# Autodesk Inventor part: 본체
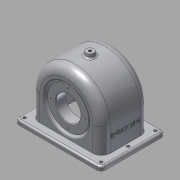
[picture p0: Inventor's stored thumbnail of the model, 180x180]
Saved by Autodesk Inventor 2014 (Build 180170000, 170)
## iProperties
Created: 2015-09
Part Number: 본체
Material: 알루미늄 6061
Document SubType Name: 판금
Designer: Owner
Density: 2.71 g/cm^3
Appearance: 알루미늄 - 평지
Sheet Metal Rule: 기본값
Author: Owner
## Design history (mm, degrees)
sketch "스케치1"
  geometry: L1 (-57, 38.5)-(57, 38.5); L2 (57, 38.5)-(57, -38.5); L3 (57, -38.5)-(-57, -38.5); L4 (-57, -38.5)-(-57, 38.5); 1 further point
  constraints: 8 end point, 2 parallel, 1 horizontal, 1 perpendicular
  dimensions: "d2" = 77 distance of L1.end L2.end; "d3" = 38.5 distance from line of L1 point (0, 0); "d4" = 114 distance of L2.end L3.end; "d8" = 57 distance from line of point (0, 0) L4
extrude "돌출1" new body sketch "스케치1" distance "d9" = 47; taper "d10" = 0 deg
sketch "스케치2"
  geometry: L1 (114, 0)-(114, 47) reference; L2 (0, 47)-(114, 47) reference; L3 (0, 47)-(114, 47); A1 r 57 centre (57, 47) between (114, 47) and (0, 47); 1 further point
  constraints: 3 point on circle, 2 end point, 2 point on line, 1 centre point, 1 midpoint, 1 perpendicular
  dimensions: "d11" = 114 diameter of A1 (derived)
extrude "돌출2" join sketch "스케치2" distance "d12" = 77; taper "d13" = 0 deg
feature "쉘1" dims "d14" = 5
fillet "모깎기1" dims "d15" = 9
sketch "스케치3"
  geometry: C1 r 31 at (57, 47); A1 r 57 centre (57, 47) between (114, 47) and (0, 47) reference; 1 further point
  constraints: 1 centre point, 1 coincident
  dimensions: "d16" = 62 diameter of C1
extrude "돌출3" join sketch "스케치3" distance "d17" = 10; taper "d18" = 0 deg
hole "구멍1" diameter "d21" = 40; stored, may be unused: countersink angle "d25" = 90 deg, drill point angle "d27" = 0 deg; dims "d19" = 10, "d20" = 10, "d22" = 6, "d23" = 4, "d24" = 2, "d26" = 8
chamfer "모따기1" distance "d28" = 1; stored, may be unused: second distance "d29" = 2, angle "d30" = 45 deg
sketch "스케치4"
  geometry: C1 r 31 at (0, 0) reference; 2 further points
  constraints: 1 vertical alignment
  dimensions: "d31" = 24 distance of C1.centre point (0, 24)
hole "구멍2" sketch "스케치4" at (0, 24) diameter "d32" = 2.459; stored, may be unused: countersink angle "d36" = 90 deg, drill point angle "d38" = 118 deg; dims "d33" = 6, "d34" = 4, "d35" = 2, "d37" = 8
sketch "스케치6"
  geometry: L1 (0, 47)-(25.941, 47); L2 (33.5, 47)-(33.5, 90) reference; L3 (33.5, 67)-(19.5, 67); L4 (19.5, 67)-(19.5, 75); L5 (19.5, 75)-(33.5, 86.747); L6 (33.5, 86.747)-(33.5, 67); 1 further point
  constraints: 10 end point, 2 perpendicular, 2 point on line, 1 collinear, 1 horizontal
  dimensions: "d43" = 47 distance from line of L1 point (0, 0); "d44" = 56 diameter of L4.end L1; "d45" = 14 distance between parallel lines of L4 L2; "d46" = 50 deg angle of L4 L5; "d47" = 40 diameter of L3 L1
revolve "회전1" sketch "스케치6" stored, may be unused: angle "d48" = 90 deg
sketch "스케치7"
  geometry: C1 r 20 at (57, -47); A1 r 57 centre (57, -47) between (0, -47) and (114, -47) reference; 1 further point
  constraints: 1 centre point, 1 coincident
  dimensions: "d49" = 40 diameter of C1
extrude "돌출4" cut sketch "스케치7" stored distance "d50" = 5; taper "d51" = 0 deg
sketch "스케치9"
  geometry: L1 (0.962, 47)-(33.255, 47); L2 (38.5, 67)-(19.5, 67) reference; L3 (35.5, 67)-(35.5, 80); L4 (35.5, 80)-(34.611, 80); L5 (19.5, 75)-(33.5, 86.747) reference; L6 (34.29, 80.883)-(38.5, 84.416); L7 (38.5, 47)-(38.5, 104) reference; L8 (38.5, 84.416)-(38.5, 67); L9 (35.5, 67)-(38.5, 67); A1 r 0.5 centre (34.611, 80.5) between (34.29, 80.883) and (34.611, 80); 2 further points
  constraints: 12 end point, 3 point on line, 2 collinear, 2 perpendicular, 2 point on circle, 2 tangent, 1 centre point, 1 horizontal, 1 parallel
  dimensions: "d52" = 47 distance from line of point (0, 0) L1; "d53" = 66 diameter of point (33.237, 80) L1; "d54" = 3 distance between parallel lines of L7 L3; "d55" = 5 distance between parallel lines of L5 L6; "d57" = 0.5 radius of A1
revolve "회전2" sketch "스케치9" stored, may be unused: angle "d56" = 90 deg
chamfer "모따기2" distance "d58" = 1; stored, may be unused: second distance "d59" = 2, angle "d60" = 45 deg
chamfer "모따기3" distance "d61" = 1; stored, may be unused: second distance "d62" = 2, angle "d63" = 45 deg
node "작업 평면2"
sketch "스케치22"
  geometry: L1 (-70, 52)-(70, 52); L2 (70, 52)-(70, -52); L3 (70, -52)-(-70, -52); L4 (-70, -52)-(-70, 52); L5 (38.416, 38.5)-(-38.416, 38.5) reference; L6 (-57, -38.5)-(57, -38.5) reference; L7 (-57, -38.5)-(-57, 38.5) reference; L8 (57, 38.5)-(-57, 38.5) reference; L9 (57, 38.5)-(57, -38.5) reference; L10 (-57, 38.5)-(57, 38.5); L11 (57, 38.5)-(57, -38.5); L12 (57, -38.5)-(-57, -38.5); L13 (-57, -38.5)-(-57, 38.5); C1 r 2.5 at (-62, 44); C2 r 2.5 at (62, 44); C3 r 2.5 at (-62, 0); C4 r 2.5 at (62, 0); C5 r 2.5 at (-62, -44); C6 r 2.5 at (62, -44); 1 further point
  constraints: 16 end point, 6 centre point, 4 parallel, 3 horizontal, 2 perpendicular, 1 vertical, 10 other
  dimensions: "d131" = 140 distance of L1.start L1.end; "d132" = 104 distance of L1.end L2.end; "d133" = 70 distance from line of point (0, 0) L4; "d134" = 52 distance from line of point (0, 0) L1; "d135" = 5 diameter of C1; "d136" = 8 distance from line of L4 C1.centre; "d137" = 8 distance from line of L1 C1.centre; "d140" = 124 distance of C1.centre C2.centre; "d143" = 44 distance of C1.centre C3.centre
extrude "돌출8" join sketch "스케치22" distance "d146" = 7; taper "d147" = 0 deg
fillet "모깎기5" dims "d93" = 3
node "작업 평면1"
sketch "스케치12"
  geometry: C1 r 6 at (0, 0); 1 further point
  constraints: 1 centre point, 1 coincident
  dimensions: "d97" = 12 diameter of C1
extrude "돌출7" join sketch "스케치12" stored distance "d98" = 7; taper "d99" = 10 deg
fillet "모깎기8" dims "d100" = 3
hole "구멍3" diameter "d103" = 4.459; stored, may be unused: countersink angle "d107" = 90 deg, drill point angle "d109" = 118 deg; dims "d101" = 10, "d102" = 10, "d104" = 15, "d105" = 4, "d106" = 2, "d108" = 8
sketch "스케치16"
  geometry: C1 r 33 at (0, 0) reference; 2 further points
  constraints: 1 vertical alignment
  dimensions: "d113" = 28 distance of C1.centre point (0, -28)
hole "구멍4" sketch "스케치16" at (0, -28) diameter "d114" = 2.459; stored, may be unused: countersink angle "d118" = 90 deg, drill point angle "d120" = 118 deg; dims "d115" = 7, "d116" = 4, "d117" = 2, "d119" = 9
sketch "스케치20"
  geometry: L1 (-40, 77)-(0, 77) reference; 2 further points
  constraints: 1 other
  dimensions: "d126" = 30 distance of point (-47, 38.5) point (-17, 38.5); "d127" = 38.5 distance from line of L1 point (-17, 38.5)
feature "엠보싱2" sketch "스케치20" dims "d2" = 77, "d3" = 38.5, "d4" = 114, "d8" = 57, "d128" = 0.5, "d129" = 0
fillet "모깎기9" dims "d148" = 7
fillet "모깎기10" dims "d149" = 3
fillet "모깎기11" dims "d150" = 14
fillet "모깎기12" dims "d151" = 0.5
node "솔리드1"
pattern_circular "원형 패턴1" dims angle "d40" = 360 deg
pattern_circular "원형 패턴2" dims angle "d122" = 360 deg
node "투영된 루프1"
other parameters: "K계수" = 4.4, "BendRadius" = 0.5 (derived), "BendReliefWidth" = 0.5 (derived), "BendReliefDepth" = 0.25 (derived), "CornerReliefSize" = 2 (derived), "SeamGap" = 0.01, "MinimumRemnant" = 1 (derived), "TransitionRadius" = 0.5 (= BendRadius), "d130" = -7
